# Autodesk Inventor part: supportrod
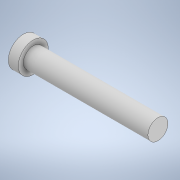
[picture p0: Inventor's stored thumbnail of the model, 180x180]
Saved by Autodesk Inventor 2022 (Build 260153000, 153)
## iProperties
Created: 2021-06
Part Number: supportrod
Material: Generic
Document SubType Name: Modeling
Designer: Chimms
Density: 1 g/cm^3
Appearance: Default
Author: Chimms
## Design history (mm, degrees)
sketch "Sketch1"
  geometry: C1 r 2 at (0, 0); 1 further point
  constraints: 1 centre point, 1 coincident
  dimensions: "d0" = 4 diameter of C1
extrude "Extrusion1" new body sketch "Sketch1" distance "d1" = 25; taper "d2" = 0 deg
sketch "Sketch2"
  geometry: C1 r 3 at (0, 0); 1 further point
  constraints: 1 centre point, 1 coincident
  dimensions: "d3" = 6 diameter of C1
extrude "Extrusion2" join sketch "Sketch2" distance "d4" = 2; taper "d5" = 0 deg
sketch "Sketch3"
  geometry: C1 r 1 at (-1.549, 0); 1 further point
  constraints: 1 centre point
  dimensions: "d6" = 2 diameter of C1
extrude "Extrusion3" join sketch "Sketch3" distance "d7" = 0.25; taper "d8" = 0 deg
body "Solid1"
